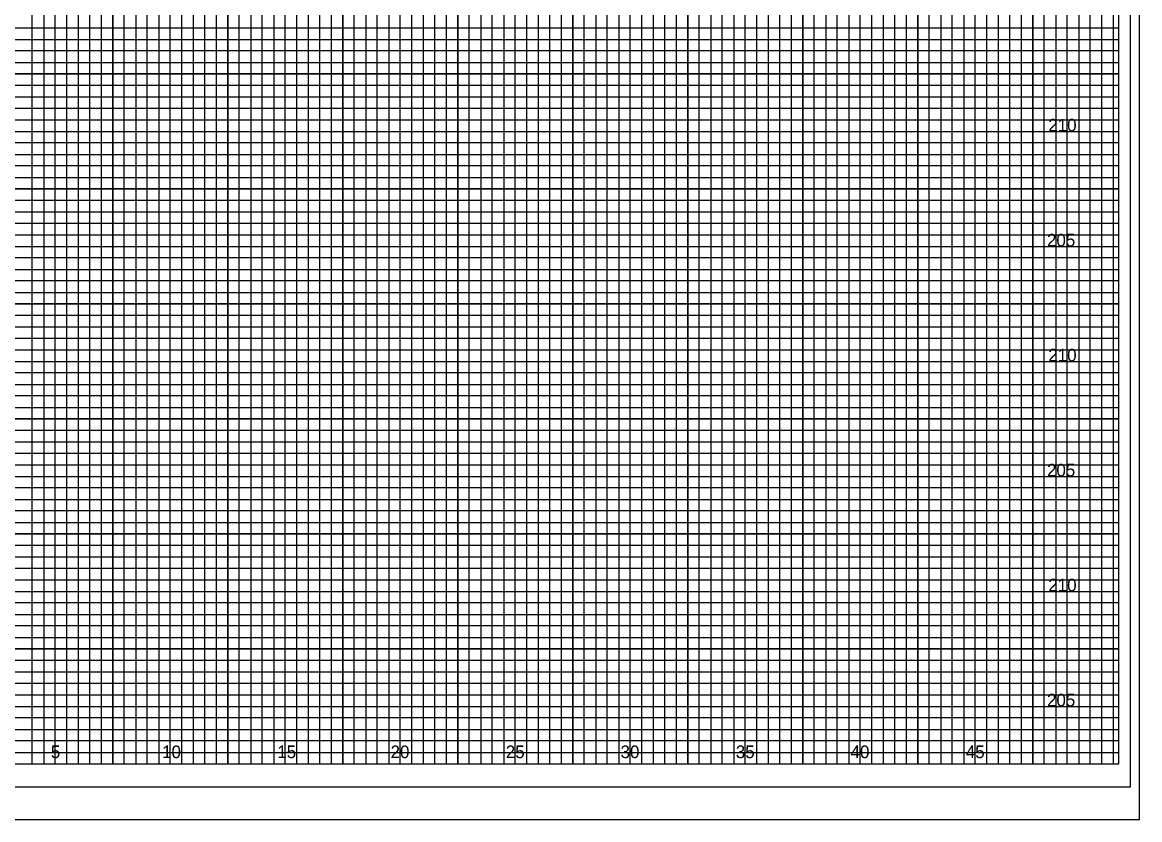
# Model space of a CAD drawing. Extents: x -4 to 103, y -2 to 492.
# Drawn here: x 54.82 to 103.4, y 68.4 to 103.07 of the extents above; entities that cross this region are included whole.
import ezdxf

# ---------------------------------------------------------------- set-up
doc = ezdxf.new("R2010")
doc.units = 0
for name, color, linetype in [('Old_Level_10', 7, 'Continuous'), ('Old_Level_16', 7, 'Continuous'), ('Old_Level_3', 7, 'Continuous'), ('Old_Level_5', 7, 'Continuous'), ('Old_Level_8', 7, 'Continuous'), ('Prop Dimension', 7, 'Continuous'), ('Prop XS Finish Grade Earthwork', 7, 'Continuous'), ('Prop XS SE Text', 7, 'Continuous'), ('Prop XSC Text', 7, 'Continuous')]:
    doc.layers.add(name, color=color, linetype=linetype)

msp = doc.modelspace()

# ---------------------------------------------------------------- linework, layer by layer
at = {"layer": 'Old_Level_10'}
for p, q in [((56.25, 70.825), (56.25, 135.825)), ((58.75, 70.825), (58.75, 135.825)), ((61.25, 70.825), (61.25, 135.825)), ((63.75, 70.825), (63.75, 135.825)), ((66.25, 70.825), (66.25, 135.825)), ((68.75, 70.825), (68.75, 135.825)), ((71.25, 70.825), (71.25, 135.825)), ((73.75, 70.825), (73.75, 135.825)), ((91.25, 70.825), (91.25, 134.25)), ((93.75, 70.825), (93.75, 134.25)), ((96.25, 70.825), (96.25, 134.25)), ((98.75, 70.825), (98.75, 134.25)), ((101.25, 70.825), (101.25, 134.25)), ((76.25, 70.825), (76.25, 132.825)), ((78.75, 70.825), (78.75, 132.825)), ((81.25, 70.825), (81.25, 132.825)), ((83.75, 70.825), (83.75, 132.825)), ((86.25, 70.825), (86.25, 132.825)), ((88.75, 70.825), (88.75, 132.825)), ((0, 100.825), (102.5, 100.825)), ((0, 98.325), (102.5, 98.325)), ((0, 95.825), (102.5, 95.825)), ((0, 93.325), (102.5, 93.325)), ((0, 90.825), (102.5, 90.825)), ((0, 88.325), (102.5, 88.325)), ((0, 85.825), (102.5, 85.825)), ((0, 83.325), (102.5, 83.325)), ((0, 80.825), (102.5, 80.825)), ((0, 78.325), (102.5, 78.325)), ((0, 75.825), (102.5, 75.825)), ((0, 73.325), (102.5, 73.325))]:
    msp.add_line(p, q, dxfattribs=at)
at = {"layer": 'Old_Level_3'}
msp.add_line((-3.5, 68.4), (103.4, 68.4), dxfattribs=at)
at = {"layer": 'Old_Level_5'}
msp.add_lwpolyline([(103.4, 138.225), (-3.5, 138.225), (-3.5, 68.4), (103.4, 68.4)], close=True, dxfattribs=at)
at = {"layer": 'Old_Level_8'}
for points in [[(56.25, 70.825), (56.25, 135.825)], [(58.75, 135.825), (58.75, 70.825), (61.25, 70.825), (61.25, 135.825)], [(63.75, 135.825), (63.75, 70.825), (66.25, 70.825), (66.25, 135.825)], [(68.75, 135.825), (68.75, 70.825), (71.25, 70.825), (71.25, 135.825)], [(73.75, 135.825), (73.75, 70.825), (76.25, 70.825), (76.25, 132.825)], [(88.75, 132.825), (88.75, 70.825), (91.25, 70.825), (91.25, 134.25)], [(93.75, 134.25), (93.75, 70.825), (96.25, 70.825), (96.25, 134.25)], [(98.75, 134.25), (98.75, 70.825), (101.25, 70.825), (101.25, 134.25)], [(78.75, 132.825), (78.75, 70.825), (81.25, 70.825), (81.25, 132.825)], [(83.75, 132.825), (83.75, 70.825), (86.25, 70.825), (86.25, 132.825)], [(0, 98.325), (102.5, 98.325), (102.5, 100.825), (0, 100.825)], [(0, 93.325), (102.5, 93.325), (102.5, 95.825), (0, 95.825)], [(0, 88.325), (102.5, 88.325), (102.5, 90.825), (0, 90.825)], [(0, 83.325), (102.5, 83.325), (102.5, 85.825), (0, 85.825)], [(0, 78.325), (102.5, 78.325), (102.5, 80.825), (0, 80.825)], [(0, 73.325), (102.5, 73.325), (102.5, 75.825), (0, 75.825)]]:
    msp.add_lwpolyline(points, dxfattribs=at)
at = {"layer": 'Prop Dimension'}
for points in [[(54.75, 70.825), (55.25, 70.825), (55.25, 135.825)], [(55.75, 135.825), (55.75, 70.825), (56.75, 70.825), (56.75, 135.825)], [(57.25, 135.825), (57.25, 70.825), (57.75, 70.825), (57.75, 135.825)], [(58.25, 135.825), (58.25, 70.825), (59.25, 70.825), (59.25, 135.825)], [(59.75, 135.825), (59.75, 70.825), (60.25, 70.825), (60.25, 135.825)], [(60.75, 135.825), (60.75, 70.825), (61.75, 70.825), (61.75, 135.825)], [(62.25, 135.825), (62.25, 70.825), (62.75, 70.825), (62.75, 135.825)], [(63.25, 135.825), (63.25, 70.825), (64.25, 70.825), (64.25, 135.825)], [(64.75, 135.825), (64.75, 70.825), (65.25, 70.825), (65.25, 135.825)], [(65.75, 135.825), (65.75, 70.825), (66.75, 70.825), (66.75, 135.825)], [(67.25, 135.825), (67.25, 70.825), (67.75, 70.825), (67.75, 135.825)], [(68.25, 135.825), (68.25, 70.825), (69.25, 70.825), (69.25, 135.825)], [(69.75, 135.825), (69.75, 70.825), (70.25, 70.825), (70.25, 135.825)], [(70.75, 135.825), (70.75, 70.825), (71.75, 70.825), (71.75, 135.825)], [(72.25, 135.825), (72.25, 70.825), (72.75, 70.825), (72.75, 135.825)], [(73.25, 135.825), (73.25, 70.825), (74.25, 70.825), (74.25, 132.825)], [(89.75, 132.825), (89.75, 70.825), (90.25, 70.825), (90.25, 134.25)], [(90.75, 134.25), (90.75, 70.825), (91.75, 70.825), (91.75, 134.25)], [(92.25, 134.25), (92.25, 70.825), (92.75, 70.825), (92.75, 134.25)], [(93.25, 134.25), (93.25, 70.825), (94.25, 70.825), (94.25, 134.25)], [(94.75, 134.25), (94.75, 70.825), (95.25, 70.825), (95.25, 134.25)], [(95.75, 134.25), (95.75, 70.825), (96.75, 70.825), (96.75, 134.25)], [(97.25, 134.25), (97.25, 70.825), (97.75, 70.825), (97.75, 134.25)], [(98.25, 134.25), (98.25, 70.825), (99.25, 70.825), (99.25, 134.25)], [(99.75, 134.25), (99.75, 70.825), (100.25, 70.825), (100.25, 134.25)], [(100.25, 134.25), (100.75, 134.25), (100.75, 70.825), (101.75, 70.825), (101.75, 134.25), (102.25, 134.25), (102.25, 70.825)], [(74.75, 132.825), (74.75, 70.825), (75.25, 70.825), (75.25, 132.825)], [(75.75, 132.825), (75.75, 70.825), (76.75, 70.825), (76.75, 132.825)], [(77.25, 132.825), (77.25, 70.825), (77.75, 70.825), (77.75, 132.825)], [(78.25, 132.825), (78.25, 70.825), (79.25, 70.825), (79.25, 132.825)], [(79.75, 132.825), (79.75, 70.825), (80.25, 70.825), (80.25, 132.825)], [(80.75, 132.825), (80.75, 70.825), (81.75, 70.825), (81.75, 132.825)], [(82.25, 132.825), (82.25, 70.825), (82.75, 70.825), (82.75, 132.825)], [(83.25, 132.825), (83.25, 70.825), (84.25, 70.825), (84.25, 132.825)], [(84.75, 132.825), (84.75, 70.825), (85.25, 70.825), (85.25, 132.825)], [(85.75, 132.825), (85.75, 70.825), (86.75, 70.825), (86.75, 132.825)], [(87.25, 132.825), (87.25, 70.825), (87.75, 70.825), (87.75, 132.825)], [(88.25, 132.825), (88.25, 70.825), (89.25, 70.825), (89.25, 132.825)], [(0, 102.325), (102.5, 102.325), (102.5, 102.825), (0, 102.825)], [(0, 101.325), (102.5, 101.325), (102.5, 101.825), (0, 101.825)], [(0, 99.825), (102.5, 99.825), (102.5, 100.325), (0, 100.325)], [(0, 98.825), (102.5, 98.825), (102.5, 99.325), (0, 99.325)], [(0, 97.325), (102.5, 97.325), (102.5, 97.825), (0, 97.825)], [(0, 96.325), (102.5, 96.325), (102.5, 96.825), (0, 96.825)], [(0, 94.825), (102.5, 94.825), (102.5, 95.325), (0, 95.325)], [(0, 93.825), (102.5, 93.825), (102.5, 94.325), (0, 94.325)], [(0, 92.325), (102.5, 92.325), (102.5, 92.825), (0, 92.825)], [(0, 91.325), (102.5, 91.325), (102.5, 91.825), (0, 91.825)], [(0, 89.825), (102.5, 89.825), (102.5, 90.325), (0, 90.325)], [(0, 88.825), (102.5, 88.825), (102.5, 89.325), (0, 89.325)], [(0, 87.325), (102.5, 87.325), (102.5, 87.825), (0, 87.825)], [(0, 86.325), (102.5, 86.325), (102.5, 86.825), (0, 86.825)], [(0, 84.825), (102.5, 84.825), (102.5, 85.325), (0, 85.325)], [(0, 83.825), (102.5, 83.825), (102.5, 84.325), (0, 84.325)], [(0, 82.325), (102.5, 82.325), (102.5, 82.825), (0, 82.825)], [(0, 81.325), (102.5, 81.325), (102.5, 81.825), (0, 81.825)], [(0, 79.825), (102.5, 79.825), (102.5, 80.325), (0, 80.325)], [(0, 78.825), (102.5, 78.825), (102.5, 79.325), (0, 79.325)], [(0, 77.325), (102.5, 77.325), (102.5, 77.825), (0, 77.825)], [(0, 76.325), (102.5, 76.325), (102.5, 76.825), (0, 76.825)], [(0, 74.825), (102.5, 74.825), (102.5, 75.325), (0, 75.325)], [(0, 73.825), (102.5, 73.825), (102.5, 74.325), (0, 74.325)], [(0, 72.325), (102.5, 72.325), (102.5, 72.825), (0, 72.825)], [(0, 71.325), (102.5, 71.325), (102.5, 71.825), (0, 71.825)]]:
    msp.add_lwpolyline(points, dxfattribs=at)
at = {"layer": 'Prop XS SE Text'}
msp.add_lwpolyline([(103, 136.825), (-2.8, 136.825), (-2.8, 69.825), (103, 69.825)], close=True, dxfattribs=at)
at = {"layer": 'Prop XSC Text'}
msp.add_lwpolyline([(102.5, 135.825), (0, 135.825), (0, 70.825), (102.5, 70.825)], close=True, dxfattribs=at)

# ---------------------------------------------------------------- texts
at = {"layer": 'Old_Level_16'}
for s, p in [('5', (56.0574, 71.075)), ('10', (60.8971, 71.075)), ('15', (65.9057, 71.075)), ('20', (70.8312, 71.075)), ('25', (75.8399, 71.075)), ('30', (80.8312, 71.075)), ('35', (85.8399, 71.075)), ('40', (90.8313, 71.075)), ('45', (95.8399, 71.075))]:
    msp.add_text(s, height=0.55, dxfattribs=at).set_placement(p)
at = {"layer": 'Prop XS Finish Grade Earthwork'}
for s, p in [('210', (99.4296, 98.325)), ('205', (99.3724, 93.325)), ('210', (99.4296, 88.325)), ('205', (99.3724, 83.325)), ('210', (99.4296, 78.325)), ('205', (99.3724, 73.325))]:
    msp.add_text(s, height=0.55, dxfattribs=at).set_placement(p)

doc.saveas('drawing.dxf')
